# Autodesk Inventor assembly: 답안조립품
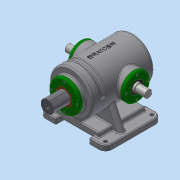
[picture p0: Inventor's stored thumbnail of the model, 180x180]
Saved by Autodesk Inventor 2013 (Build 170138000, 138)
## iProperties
Created: 2018-06
Part Number: 답안조립품
Document SubType Name: Assembly
Designer: Administrator
Author: Administrator
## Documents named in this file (13)
- C:\Users\Administrator\Desktop\380628V1010\답안조립품.iam
- C:\Users\Administrator\Desktop\380628V1010\본체.ipt
- C:\Users\Administrator\Desktop\380628V1010\가변스프링.ipt
- C:\Users\Administrator\Desktop\380628V1010\베어링 6205.ipt
- 베어링 6205.ipt
- C:\Users\Administrator\Desktop\380628V1010\볼트 M4.ipt
- C:\Users\Administrator\Desktop\380628V1010\부시.ipt
- C:\Users\Administrator\Desktop\380628V1010\슬라이드 커버.ipt
- C:\Users\Administrator\Desktop\380628V1010\슬라이드.ipt
- C:\Users\Administrator\Desktop\380628V1010\오일실.ipt
- 오일실.ipt
- C:\Users\Administrator\Desktop\380628V1010\축 커버.ipt
- C:\Users\Administrator\Desktop\380628V1010\편심축.ipt
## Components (1 placed, 1 different names)
1. 가변스프링:1
